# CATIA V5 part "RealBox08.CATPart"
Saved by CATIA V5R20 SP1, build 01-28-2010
Part number: RealBox
Bounding box of the stored display mesh (mm): x -6 to 186, y 0 to 183, z 0 to 76.5
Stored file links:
  C:\Users\elisf\Desktop\Elis\ENSINOFATEC\MAV5\DIP\Labirinto\RealBox\RealBox08.CATPart
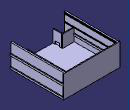
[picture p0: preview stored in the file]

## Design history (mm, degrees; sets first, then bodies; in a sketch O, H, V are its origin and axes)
Body1 (main body)
  Sketch1 on xy-plane, origin (0, 0, 0), H (1, 0, 0), V (0, 1, 0)
    line L1 (0, 0) -> (180, 0)
    line L2 (180, 0) -> (180, 180)
    line L3 (180, 180) -> (0, 180)
    line L4 (0, 180) -> (0, 0)
    length L1 = 180
    length L4 = 180
    horizontal: L1 H, L3 H
    vertical: L2 V, L4 V
  Pad1: profile Sketch1, direction (0, 0, 1), length 3
  Sketch2 on end face of Pad1, origin (0, 0, 3), H (1, 0, 0), V (0, 1, 0)
    reference projected line E1 (0, 0) -> (180, 0) from edge [face of Pad1 from Sketch1.L1 | end face of Pad1]
    reference projected line E2 (0, 180) -> (0, 0) from edge [face of Pad1 from Sketch1.L4 | end face of Pad1]
    point P5 (0, 30)
    line L1 (0, 30) -> (40, 30)
    line L2 (40, 30) -> (40, 33)
    line L3 (40, 33) -> (0, 33)
    point P8 (0, 33)
    line L4 (0, 33) -> (0, 30)
    line L5 (40, 30) -> (40, 0)
    point P9 (40, 0)
    line L6 (40, 0) -> (37, 0)
    line L7 (37, 0) -> (37, 30)
    point P11 (37, 30)
    line L8 (37, 30) -> (40, 30)
    length L4 = 3
    length L1 = 40
    distance L1 E1 = 30
    length L6 = 3
    coincidence: P5 E2, P8 E2, P9 E1, P11 L1
    horizontal: L1 H, L3 H, L6 H, L8 H
    vertical: L2 V, L4 V, L5 V, L7 V
  Pad2: profile Sketch2, direction (0, 0, 1), length 42
  Sketch3 on face of Pad2 from Sketch2.L5, origin (40, 0, 0), H (0, 1, 0), V (0, 0, 1)
    reference projected line E1 (0, 3) -> (180, 3) from edge [face of Pad1 from Sketch1.L2 | end face of Pad1]
    reference projected line E2 (0, 3) -> (0, 45) from edge [face of Pad2 from Sketch2.L5 | face of Pad2]
    reference projected line E3 (30, 3) -> (30, 45) from edge [face of Pad2 from Sketch2.L2 | face of Pad2 from Sketch2.L1]
    construction line L1 (15, 3) -> (15, 14.6719)
    point P7 (15, 3)
    line L2 (22.5, 3) -> (22.5, 13)
    line L3 (22.5, 13) -> (7.5, 13)
    line L4 (7.5, 13) -> (7.5, 3)
    point P12 (7.5, 3)
    line L5 (7.5, 3) -> (22.5, 3)
    length L5 = 15
    length L4 = 10
    coincidence: P7 E1, P12 E1
    vertical: L1 V, L2 V, L4 V
    symmetry: E2 E3 L1, L2 L4 L1
    horizontal: L3 H, L5 H
  Pocket1: profile Sketch3, direction (-1, 0, 0), length 3
  Sketch4 on face of Pocket1, origin (0, 0, 3), H (1, 0, 0), V (0, 1, 0)
    reference projected line E3 (180, 180) -> (0, 180) from edge [face of Pad1 from Sketch1.L3 | face of Pocket1]
    line L1 (0, 33) -> (3, 33)
    line L2 (3, 33) -> (3, 180)
    point P8 (3, 180)
    line L3 (3, 180) -> (0, 180)
    line L4 (0, 180) -> (0, 33)
    length L1 = 3
    horizontal: L1 H, L3 H
    coincidence: P8 E3
    vertical: L2 V, L4 V
  Pad3: profile Sketch4, direction (0, 0, 1), length 26
  Sketch5 on face of Pocket1, origin (0, 0, 3), H (1, 0, 0), V (0, 1, 0)
    reference projected line E10 (40, 0) -> (180, 0) from edge [face of Pad2 | face of Pocket1]
    reference projected line E11 (180, 0) -> (180, 180) from edge [face of Pad1 from Sketch1.L2 | face of Pocket1]
    reference projected line E12 (180, 180) -> (3, 180) from edge [face of Pad3 | face of Pocket1]
    construction line L1 (130, 0) -> (130, 51.8121)
    point P35 (130, 0)
    line L2 (130, 0) -> (127, 0)
    line L3 (127, 0) -> (127, 180)
    point P38 (127, 180)
    line L4 (127, 180) -> (130, 180)
    point P39 (130, 180)
    line L5 (130, 180) -> (130, 0)
    distance L1 E11 = 50
    length L2 = 3
    coincidence: P35 E10, P38 E12, P39 L1
    vertical: L1 V, L3 V, L5 V
    horizontal: L2 H, L4 H
  Pad4: profile Sketch5, direction (0, 0, 1), length 26
  Sketch6 on face of Pad4, origin (0, 0, 0), H (1, 0, 0), V (0, 0, 1)
    line L1 (-3, 76.5) -> (0, 76.5)
    point P4 (0, 76.5)
    projected line E2 (0, 45) -> (40, 45) from edge [face of Pad2 from Sketch2.L1 | end face of Pad2]
    projected line E3 (0, 45) -> (180, 45) from edge [face of Pad2 from Sketch2.L1 | end face of Pad2]
    projected line E4 (180, 0) -> (180, 3) from edge [face of Pad1 from Sketch1.L2 | face of Pad4]
    projected line E5 (180, 0) -> (180, 45) from edge [face of Pad1 from Sketch1.L2 | face of Pad4]
    line L2 (183, 76.5) -> (178, 76.5)
    line L3 (178, 76.5) -> (178, 74.5)
    line L4 (178, 74.5) -> (180, 74.5)
    point P13 (180, 74.5)
    line L5 (180, 74.5) -> (180, 71.5)
    line L6 (180, 71.5) -> (178, 71.5)
    point P15 (178, 71.5)
    line L7 (178, 71.5) -> (178, 69.5)
    line L8 (178, 69.5) -> (180, 69.5)
    point P17 (180, 69.5)
    line L9 (180, 47) -> (178, 47)
    point P19 (178, 47)
    line L10 (178, 47) -> (178, 45)
    line L11 (178, 45) -> (180, 45)
    point P21 (180, 45)
    line L12 (180, 45) -> (180, 0)
    point P22 (2, 76.5)
    line L13 (2, 76.5) -> (0, 76.5)
    line L14 (2, 45) -> (2, 47)
    line L15 (2, 47) -> (0, 47)
    point P25 (0, 47)
    line L16 (0, 47) -> (0, 70)
    line L17 (0, 70) -> (2, 70)
    point P27 (2, 70)
    line L18 (0, 71.5) -> (2, 71.5)
    point P29 (2, 71.5)
    line L19 (0, 74.5) -> (2, 74.5)
    point P31 (2, 74.5)
    line L20 (2, 74.5) -> (2, 76.5)
    line L21 (2, 70) -> (2, 71.5)
    line L22 (2, 45) -> (0, 45)
    line L23 (0, 74.5) -> (0, 71.5)
    reference projected line E6 (40, 3) -> (40, 45) from edge [face of Pad2 from Sketch2.L5 | face of Pad4]
    reference projected line E7 (127, 29) -> (130, 29) from edge [face of Pad4 | end face of Pad4]
    line L24 (0, 45) -> (0, 0)
    line L25 (180, 47) -> (180, 69.5)
    line L26 (180, 0) -> (186, 0)
    line L27 (186, 0) -> (186, 6)
    line L28 (186, 6) -> (183, 6)
    line L29 (183, 6) -> (183, 39)
    line L30 (183, 39) -> (186, 39)
    point P41 (186, 39)
    line L31 (186, 39) -> (186, 45)
    line L32 (186, 45) -> (183, 45)
    point P43 (183, 45)
    line L33 (183, 45) -> (183, 76.5)
    line L34 (0, 0) -> (-6, 0)
    line L35 (-6, 0) -> (-6, 6)
    line L36 (-6, 6) -> (-3, 6)
    line L37 (-3, 6) -> (-3, 39)
    line L38 (-3, 39) -> (-6, 39)
    point P48 (-6, 39)
    line L39 (-6, 39) -> (-6, 45)
    line L40 (-6, 45) -> (-3, 45)
    point P50 (-3, 45)
    line L41 (-3, 45) -> (-3, 76.5)
    length L21 = 1.5
    length L14 = 2
    length L20 = 2
    length L10 = 2
    length L13 = 2
    length L23 = 3
    length E6 = 42 (reference)
    distance E7 E2 = 16 (reference)
    length L4 = 2
    length L7 = 2
    length L5 = 3
    length L3 = 2
    length L27 = 6
    length L26 = 6
    distance L29 L12 = 3
    distance L2 L26 = 76.5
    length L31 = 6
    distance L30 L28 = 33
    length L35 = 6
    length L34 = 6
    length L39 = 6
    distance L37 L24 = 3
    distance L1 L34 = 76.5
    distance L38 L36 = 33
    coincidence: P4 V, P13 E4, P15 L3, P17 E4, P19 L3, P21 E4, P22 L1, P25 V, P27 L14, P29 L14, P31 L14, L11 E2, L23 L16, L22 E2, P41 L27, P43 L29, P48 L35, P50 L37
    horizontal: L1 H, L2 H, L4 H, L6 H, L8 H, L9 H, L11 H, L13 H, L15 H, L17 H, L18 H, L19 H, L22 H, L26 H, L28 H, L30 H, L32 H, L34 H, L36 H, L38 H, L40 H
    vertical: L3 V, L5 V, L7 V, L10 V, L12 V, L14 V, L16 V, L20 V, L21 V, L23 V, L24 V, L25 V, L27 V, L29 V, L31 V, L33 V, L35 V, L37 V, L39 V, L41 V
  Pad5: profile Sketch6, direction (0, 1, 0), length 180
  Sketch7 on face of Pad5, origin (0, 0, 0), H (1, 0, 0), V (0, 0, 1)
    reference projected line E1 (0, 3) -> (37, 3) from edge [face of Pad5 | face of Pocket1]
    reference projected line E2 (-6, 0) -> (186, 0) from edge [face of Pad5 | face of Pad5]
    construction line L1 (0, 3) -> (0, 0)
    construction line L2 (37, 3) -> (37, 0)
    point P5 (37, 0)
    construction line L3 (18.5, 3) -> (18.5, 0)
    point P6 (18.5, 3)
    point P7 (18.5, 0)
    line L4 (0, 3) -> (18.5, 1.5)
    point P8 (18.5, 1.5)
    line L5 (18.5, 1.5) -> (18.5, 3)
    line L6 (18.5, 3) -> (0, 3)
    vertical: L1 V, L2 V, L3 V, L5 V
    coincidence: P5 E2, P7 E2
    midpoint: P6 E1, P8 L3
    horizontal: L6 H
  Pocket2: profile Sketch7, direction (0, 1, 0), length 30
  Sketch8 on face of Pad5, origin (0, 0, 0), H (1, 0, 0), V (0, 0, 1)
    line L1 (18.5, 3) -> (18.5, 1.5)
    line L2 (18.5, 1.5) -> (37, 3)
    line L3 (37, 3) -> (18.5, 3)
    length L3 = 18.5
    vertical: L1 V
    horizontal: L3 H
  Pocket3: profile Sketch8, direction (0, 1, 0), length 30
  Sketch9 on face of Pocket3 from Sketch8.L2, origin (0, 0, 0), H (0, -1, 0), V (0.9967, 0, 0.0808)
    reference projected line E1 (0, 18.5607) -> (-30, 18.5607) from edge [face of Pocket3 from Sketch8.L2 | face of Pocket2 from Sketch7.L4]
    arc A1 centre (-15, 18.5607) radius 7.5 from (-7.5, 18.5607) to (-22.5, 18.5607) ccw
    point P3 (-15, 18.5607)
    point P4 (-7.5, 18.5607)
    point P5 (-22.5, 18.5607)
    line L1 (-7.5, 18.5607) -> (-22.5, 18.5607)
    radius A1 = 7.5
    midpoint: P3 E1
    coincidence: P4 E1, P5 E1
    horizontal: L1 H
  Pocket4: profile Sketch9, direction (0.0808, 0, -0.9967), length 1
  Sketch10 on face of Pad5, origin (0, 0, 0), H (1, 0, 0), V (0, 0, 1)
    reference projected line E2 (186, 0) -> (186, 6) from edge [face of Pad5 from Sketch6.L27 | face of Pad5]
    construction line L1 (186, 3) -> (183, 3)
    point P5 (186, 3)
    circle A1 centre (183, 3) radius 1.5
    reference projected line E3 (-6, 6) -> (-6, 0) from edge [face of Pad5 from Sketch6.L35 | face of Pad5]
    construction line L2 (-6, 3) -> (-3, 3)
    point P9 (-6, 3)
    circle A2 centre (-3, 3) radius 1.5
    reference projected line E5 (-6, 45) -> (-6, 39) from edge [face of Pad5 from Sketch6.L39 | face of Pad5]
    reference projected line E7 (186, 39) -> (186, 45) from edge [face of Pad5 from Sketch6.L31 | face of Pad5]
    construction line L3 (186, 42) -> (183, 42)
    point P19 (186, 42)
    construction line L4 (-6, 42) -> (-3, 42)
    point P21 (-6, 42)
    circle A3 centre (-3, 42) radius 1.5
    circle A4 centre (183, 42) radius 1.5
    length L1 = 3
    radius A1 = 1.5
    length L2 = 3
    radius A2 = 1.5
    length L3 = 3
    length L4 = 3
    radius A3 = 1.5
    radius A4 = 1.5
    midpoint: P5 E2, P9 E3, P19 E7, P21 E5
    horizontal: L1 H, L2 H, L3 H, L4 H
  MultiPocket1: profile Sketch10, domains (length 15; length 15; length 15; length 15)
  Sketch11 on face of Pad5, origin (0, 0, 0), H (1, 0, 0), V (0, -1, 0)
    line L1 (-6, -180) -> (186, -180)
    line L2 (186, -180) -> (186, -183)
    line L3 (186, -183) -> (-6, -183)
    line L4 (-6, -183) -> (-6, -180)
    length L4 = 3
    horizontal: L1 H, L3 H
    vertical: L2 V, L4 V
  Pad6: profile Sketch11, direction (0, 0, 1), length 76.5
  Sketch12 on face of Pad3 from Sketch4.L2, origin (3, 0, 0), H (0, 1, 0), V (0, 0, 1)
    reference projected line E3 (180, 3) -> (180, 29) from edge [face of Pad6 from Sketch11.L1 | face of Pad3 from Sketch4.L2]
    line L1 (33, 3) -> (180, 3)
    line L2 (180, 3) -> (180, 23)
    line L3 (180, 23) -> (33, 23)
    line L4 (33, 23) -> (33, 3)
    point P8 (180, 23)
    length L4 = 20
    horizontal: L1 H, L3 H
    vertical: L2 V, L4 V
    coincidence: P8 E3
  Pocket5: profile Sketch12, direction (-1, 0, 0), length 3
